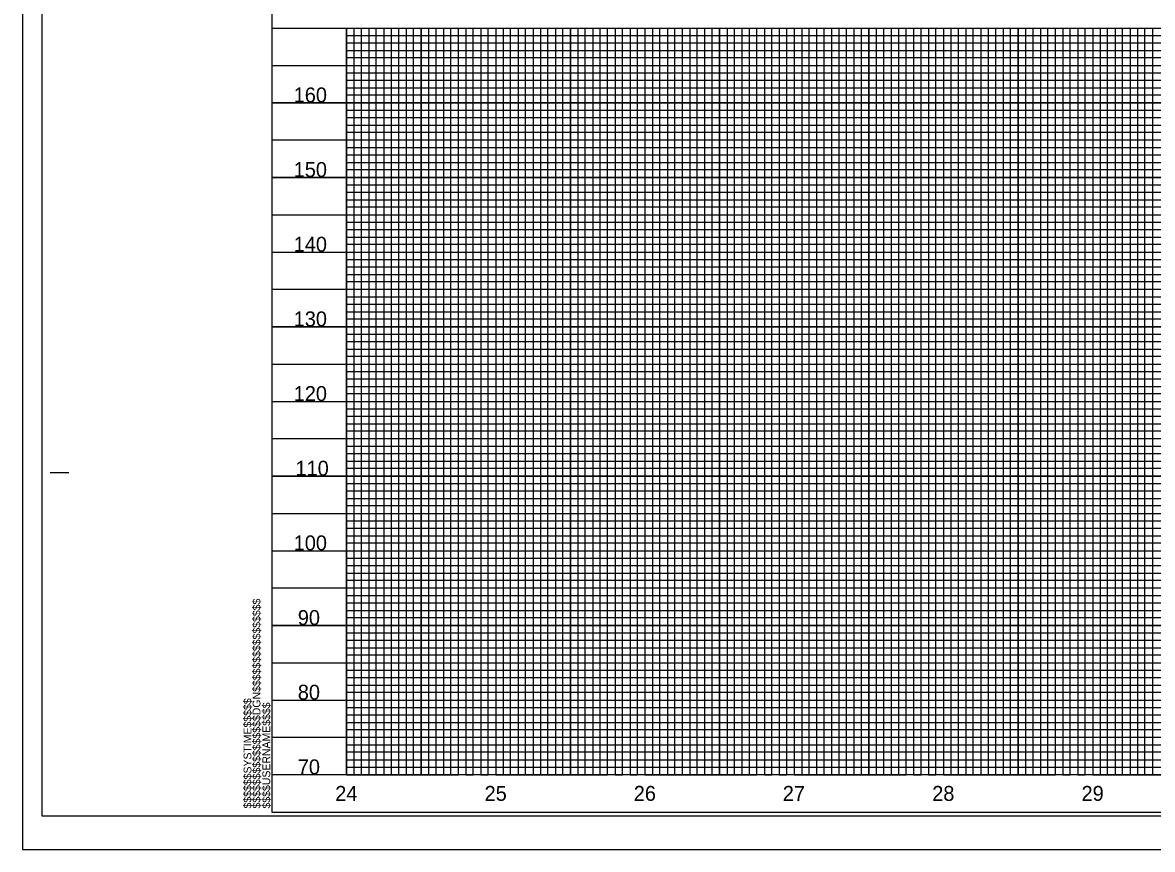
# Model space of a CAD drawing. Extents: x 1779926 to 1781610, y 602514 to 621564.
# Drawn here: x 1779926 to 1780683, y 602514 to 603068 of the extents above; entities that cross this region are included whole.
import ezdxf

# ---------------------------------------------------------------- set-up
doc = ezdxf.new("R2010")
doc.units = 0
for name, color, linetype in [('Exist Vertical Profile Horizontal Axis Label Major', 7, 'Continuous'), ('Exist Vertical Profile Vertical Axis Label', 7, 'Continuous'), ('Scratch_Level_0', 7, 'Continuous'), ('Sheet DOT Grid CELL', 7, 'Continuous'), ('Sheet Layout Profile Border Port 2', 7, 'Continuous'), ('Sheet Plot Border Inside CELL', 7, 'Continuous'), ('Sheet Plot Border Outside CELL', 7, 'Continuous'), ('Sheet Profile CELL', 7, 'Continuous'), ('Sheet Profile Grid Major CELL', 7, 'Continuous'), ('Sheet Profile Grid Middle CELL', 7, 'Continuous'), ('Sheet Profile Grid Minor CELL', 7, 'Continuous')]:
    doc.layers.add(name, color=color, linetype=linetype)

msp = doc.modelspace()

# ---------------------------------------------------------------- linework, layer by layer
at = {"layer": 'Scratch_Level_0'}
msp.add_lwpolyline([(1780142.96, 602564.45), (1780142.96, 603064.45), (1781542.96, 603064.45), (1781542.96, 602564.45)], close=True, dxfattribs=at)
at = {"layer": 'Sheet DOT Grid CELL'}
for p, q in [((1780092.96, 603064.45), (1781592.85, 603064.45)), ((1780142.96, 603064.45), (1780142.96, 602564.45)), ((1780192.96, 603064.45), (1780192.96, 602564.45)), ((1780242.96, 603064.45), (1780242.96, 602564.45)), ((1780292.96, 603064.45), (1780292.96, 602564.45)), ((1780342.96, 603064.45), (1780342.96, 602564.45)), ((1780392.96, 603064.45), (1780392.96, 602564.45)), ((1780442.96, 603064.45), (1780442.96, 602564.45)), ((1780492.96, 603064.45), (1780492.96, 602564.45)), ((1780542.96, 603064.45), (1780542.96, 602564.45)), ((1780592.96, 603064.45), (1780592.96, 602564.45)), ((1780642.96, 603064.45), (1780642.96, 602564.45)), ((1780092.96, 603014.45), (1781592.85, 603014.45)), ((1780092.96, 602964.45), (1781592.85, 602964.45)), ((1780092.96, 602914.45), (1781592.85, 602914.45)), ((1780092.96, 602864.45), (1781592.85, 602864.45)), ((1780092.96, 602814.45), (1781592.85, 602814.45)), ((1780092.96, 602764.45), (1781592.85, 602764.45)), ((1780092.96, 602714.45), (1781592.85, 602714.45)), ((1780092.96, 602664.45), (1781592.85, 602664.45)), ((1780092.96, 602614.45), (1781592.85, 602614.45))]:
    msp.add_line(p, q, dxfattribs=at)
at = {"layer": 'Sheet Layout Profile Border Port 2'}
msp.add_lwpolyline([(1780142.96, 603064.45), (1781542.96, 603064.45), (1781542.96, 602564.45), (1780142.96, 602564.45)], close=True, dxfattribs=at)
msp.add_lwpolyline([(1780142.96, 603064.45), (1781542.96, 603064.45), (1781542.96, 602564.45), (1780142.96, 602564.45)], close=True, dxfattribs=at)
at = {"layer": 'Sheet Plot Border Inside CELL'}
msp.add_lwpolyline([(1779938.96, 602536.9), (1781605.46, 602536.9), (1781605.46, 603592), (1779938.96, 603592)], close=True, dxfattribs=at)
at = {"layer": 'Sheet Plot Border Outside CELL'}
msp.add_lwpolyline([(1779925.96, 602514.45), (1781609.96, 602514.45), (1781609.96, 603614.45), (1779925.96, 603614.45)], close=True, dxfattribs=at)
at = {"layer": 'Sheet Profile CELL'}
for p, q in [((1780092.96, 603064.45), (1781592.96, 603064.45)), ((1779944.46, 602766.95), (1779956.96, 602766.95)), ((1781592.96, 602564.45), (1780092.96, 602564.45)), ((1780092.96, 602539.45), (1781592.96, 602539.45)), ((1780092.96, 602539.45), (1780092.96, 602539.45)), ((1780092.96, 602539.45), (1780092.96, 602539.45)), ((1780092.96, 602539.45), (1780092.96, 602539.45)), ((1780092.96, 602539.45), (1780092.96, 602539.45)), ((1780092.96, 602539.45), (1780092.96, 602539.45)), ((1780092.96, 602539.45), (1780092.96, 602539.45)), ((1780092.96, 602539.45), (1780092.96, 602539.45))]:
    msp.add_line(p, q, dxfattribs=at)
msp.add_lwpolyline([(1781592.96, 603589.45), (1780092.96, 603589.45), (1780092.96, 602539.45), (1781592.96, 602539.45)], close=True, dxfattribs=at)
msp.add_lwpolyline([(1780130.46, 602539.45), (1780130.46, 602539.45)], dxfattribs=at)
at = {"layer": 'Sheet Profile Grid Major CELL'}
for p, q in [((1780592.96, 603064.45), (1780642.96, 603064.45)), ((1780092.96, 602564.45), (1780092.96, 602564.45))]:
    msp.add_line(p, q, dxfattribs=at)
for points in [[(1780142.96, 603064.45), (1780142.96, 602564.45), (1780192.96, 602564.45), (1780192.96, 603064.45), (1780242.96, 603064.45), (1780242.96, 602564.45), (1780292.96, 602564.45), (1780292.96, 603064.45), (1780342.96, 603064.45), (1780342.96, 602564.45), (1780392.96, 602564.45), (1780392.96, 603064.45), (1780442.96, 603064.45), (1780442.96, 602564.45), (1780492.96, 602564.45), (1780492.96, 603064.45), (1780542.96, 603064.45), (1780542.96, 602564.45), (1780592.96, 602564.45), (1780592.96, 603064.45), (1780642.96, 603064.45), (1780642.96, 602564.45), (1780692.96, 602564.45)], [(1781592.96, 603014.45), (1780092.96, 603014.45)], [(1781592.96, 602964.45), (1780092.96, 602964.45), (1780092.96, 602914.45), (1781592.96, 602914.45)], [(1781592.96, 602864.45), (1780092.96, 602864.45), (1780092.96, 602814.45), (1781592.96, 602814.45)], [(1781592.96, 602764.45), (1780092.96, 602764.45), (1780092.96, 602714.45), (1781592.96, 602714.45)], [(1781592.96, 602664.45), (1780092.96, 602664.45), (1780092.96, 602664.45), (1780092.96, 602614.45), (1781592.96, 602614.45)], [(1781592.96, 602564.45), (1780092.96, 602564.45)]]:
    msp.add_lwpolyline(points, dxfattribs=at)
at = {"layer": 'Sheet Profile Grid Middle CELL'}
for points in [[(1780117.96, 603064.45), (1780167.96, 603064.45), (1780167.96, 602564.45), (1780217.96, 602564.45), (1780217.96, 603064.45), (1780267.96, 603064.45), (1780267.96, 602564.45), (1780317.96, 602564.45), (1780317.96, 603064.45), (1780367.96, 603064.45), (1780367.96, 602564.45), (1780417.96, 602564.45), (1780417.96, 603064.45), (1780467.96, 603064.45), (1780467.96, 602564.45), (1780517.96, 602564.45), (1780517.96, 603064.45), (1780567.96, 603064.45), (1780567.96, 602564.45), (1780617.96, 602564.45), (1780617.96, 603064.45), (1780667.96, 603064.45), (1780667.96, 602564.45), (1780717.96, 602564.45)], [(1780092.96, 603039.45), (1781592.96, 603039.45)], [(1781592.96, 602989.45), (1780092.96, 602989.45), (1780092.96, 602939.45), (1781592.96, 602939.45)], [(1781592.96, 602889.45), (1780092.96, 602889.45), (1780092.96, 602839.45), (1781592.96, 602839.45)], [(1781592.96, 602789.45), (1780092.96, 602789.45), (1780092.96, 602739.45), (1781592.96, 602739.45)], [(1781592.96, 602689.45), (1780092.96, 602689.45), (1780092.96, 602639.45), (1781592.96, 602639.45)], [(1781592.96, 602589.45), (1780092.96, 602589.45)]]:
    msp.add_lwpolyline(points, dxfattribs=at)
at = {"layer": 'Sheet Profile Grid Minor CELL'}
for p, q in [((1780142.96, 603059.45), (1781542.96, 603059.45)), ((1781542.96, 603054.45), (1780142.96, 603054.45)), ((1780142.96, 603049.45), (1781542.96, 603049.45)), ((1781542.96, 603044.45), (1780142.96, 603044.45)), ((1780142.96, 603034.45), (1781542.96, 603034.45)), ((1781542.96, 603029.45), (1780142.96, 603029.45)), ((1780142.96, 603024.45), (1781542.96, 603024.45)), ((1781542.96, 603019.45), (1780142.96, 603019.45)), ((1780142.96, 603009.45), (1781542.96, 603009.45)), ((1781542.96, 603004.45), (1780142.96, 603004.45)), ((1780142.96, 602999.45), (1781542.96, 602999.45)), ((1781542.96, 602994.45), (1780142.96, 602994.45)), ((1780142.96, 602984.45), (1781542.96, 602984.45)), ((1781542.96, 602979.45), (1780142.96, 602979.45)), ((1780142.96, 602974.45), (1781542.96, 602974.45)), ((1781542.96, 602969.45), (1780142.96, 602969.45)), ((1780142.96, 602959.45), (1781542.96, 602959.45)), ((1781542.96, 602954.45), (1780142.96, 602954.45)), ((1780142.96, 602949.45), (1781542.96, 602949.45)), ((1781542.96, 602944.45), (1780142.96, 602944.45)), ((1780142.96, 602934.45), (1781542.96, 602934.45)), ((1781542.96, 602929.45), (1780142.96, 602929.45)), ((1780142.96, 602924.45), (1781542.96, 602924.45)), ((1781542.96, 602919.45), (1780142.96, 602919.45)), ((1780142.96, 602909.45), (1781542.96, 602909.45)), ((1781542.96, 602904.45), (1780142.96, 602904.45)), ((1780142.96, 602899.45), (1781542.96, 602899.45)), ((1781542.96, 602894.45), (1780142.96, 602894.45)), ((1780142.96, 602884.45), (1781542.96, 602884.45)), ((1781542.96, 602879.45), (1780142.96, 602879.45)), ((1780142.96, 602874.45), (1781542.96, 602874.45)), ((1781542.96, 602869.45), (1780142.96, 602869.6)), ((1780142.96, 602859.45), (1781542.96, 602859.45)), ((1781542.96, 602854.45), (1780142.96, 602854.45)), ((1780142.96, 602849.45), (1781542.96, 602849.45)), ((1781542.96, 602844.45), (1780142.96, 602844.45)), ((1780142.96, 602834.45), (1781542.96, 602834.45)), ((1781542.96, 602829.45), (1780142.96, 602829.45)), ((1780142.96, 602824.45), (1781542.96, 602824.45)), ((1781542.96, 602819.45), (1780142.96, 602819.45)), ((1780142.96, 602809.45), (1781542.96, 602809.45)), ((1781542.96, 602804.45), (1780142.96, 602804.45)), ((1780142.96, 602799.45), (1781542.96, 602799.45)), ((1781542.96, 602794.45), (1780142.96, 602794.45)), ((1780142.96, 602784.45), (1781542.96, 602784.45)), ((1781542.96, 602779.45), (1780142.96, 602779.45)), ((1780142.96, 602774.45), (1781542.96, 602774.45)), ((1781542.96, 602769.45), (1780142.96, 602769.45)), ((1780142.96, 602759.45), (1781542.96, 602759.45)), ((1781542.96, 602754.45), (1780142.96, 602754.45)), ((1780142.96, 602749.45), (1781542.96, 602749.45)), ((1781542.96, 602744.45), (1780142.96, 602744.45)), ((1780142.96, 602734.45), (1781542.96, 602734.45)), ((1781542.96, 602729.45), (1780142.96, 602729.45)), ((1780142.96, 602724.45), (1781542.96, 602724.45)), ((1781542.96, 602719.45), (1780142.96, 602719.45)), ((1780142.96, 602709.45), (1781542.96, 602709.45)), ((1781542.96, 602704.45), (1780142.96, 602704.45)), ((1780142.96, 602699.45), (1781542.96, 602699.45)), ((1781542.96, 602694.45), (1780142.96, 602694.45)), ((1780142.96, 602684.45), (1781542.96, 602684.45)), ((1781542.96, 602679.45), (1780142.96, 602679.45)), ((1780142.96, 602674.45), (1781542.96, 602674.45)), ((1781542.96, 602669.45), (1780142.96, 602669.45)), ((1780142.96, 602659.45), (1781542.96, 602659.45)), ((1781542.96, 602654.45), (1780142.96, 602654.45)), ((1780142.96, 602649.45), (1781542.96, 602649.45)), ((1781542.96, 602644.45), (1780142.96, 602644.45)), ((1780142.96, 602634.45), (1781542.96, 602634.45)), ((1781542.96, 602629.45), (1780142.96, 602629.45)), ((1780142.96, 602624.45), (1781542.96, 602624.45)), ((1781542.96, 602619.45), (1780142.96, 602619.45)), ((1780142.96, 602609.45), (1781542.96, 602609.45)), ((1781542.96, 602604.45), (1780142.96, 602604.45)), ((1780142.96, 602599.45), (1781542.96, 602599.45)), ((1781542.96, 602594.45), (1780142.96, 602594.45)), ((1780142.96, 602584.45), (1781542.96, 602584.45)), ((1781542.96, 602579.45), (1780142.96, 602579.45)), ((1780142.96, 602574.45), (1781542.96, 602574.45)), ((1780142.96, 602569.45), (1781542.96, 602569.45))]:
    msp.add_line(p, q, dxfattribs=at)
for points in [[(1780142.96, 603064.45), (1780147.96, 603064.45), (1780147.96, 602564.45), (1780152.96, 602564.45), (1780152.96, 603064.45), (1780157.96, 603064.45), (1780157.96, 602564.45), (1780162.96, 602564.45), (1780162.96, 603064.45), (1780172.96, 603064.45), (1780172.96, 602564.45), (1780177.96, 602564.45), (1780177.96, 603064.45), (1780182.96, 603064.45), (1780182.96, 602564.45), (1780187.96, 602564.45), (1780197.96, 602564.45), (1780202.96, 602564.45), (1780202.96, 603064.45), (1780207.96, 603064.45), (1780207.96, 602564.45), (1780212.96, 602564.45), (1780212.96, 603064.45), (1780222.96, 603064.45), (1780222.96, 602564.45), (1780227.96, 602564.45), (1780227.96, 603064.45), (1780232.96, 603064.45), (1780232.96, 602564.45), (1780237.96, 602564.45), (1780237.96, 603064.45), (1780247.96, 603064.45), (1780247.96, 602564.45), (1780252.96, 602564.45), (1780252.96, 603064.45), (1780257.96, 603064.45), (1780257.96, 602564.45), (1780262.96, 602564.45), (1780262.96, 603064.45), (1780272.96, 603064.45), (1780272.96, 602564.45), (1780277.96, 602564.45), (1780277.96, 603064.45), (1780282.96, 603064.45), (1780282.96, 602564.45), (1780287.96, 602564.45), (1780287.96, 603064.45), (1780297.96, 603064.45), (1780297.96, 602564.45), (1780302.96, 602564.45), (1780302.96, 603064.45), (1780307.96, 603064.45), (1780307.96, 602564.45), (1780312.96, 602564.45), (1780312.96, 603064.45), (1780322.96, 603064.45), (1780322.96, 602564.45), (1780327.96, 602564.45), (1780327.96, 603064.45), (1780332.96, 603064.45), (1780332.96, 602564.45), (1780337.96, 602564.45), (1780337.96, 603064.45), (1780347.96, 603064.45), (1780347.96, 602564.45), (1780352.96, 602564.45), (1780352.96, 603064.45), (1780357.96, 603064.45), (1780357.96, 602564.45)], [(1780187.96, 602564.45), (1780187.96, 603064.45), (1780197.96, 603064.45), (1780197.96, 602564.45)], [(1780357.96, 602564.45), (1780362.96, 602564.45), (1780362.96, 603064.45), (1780372.96, 603064.45), (1780372.96, 602564.45), (1780377.96, 602564.45), (1780377.96, 603064.45), (1780382.96, 603064.45), (1780382.96, 602564.45), (1780387.96, 602564.45), (1780387.96, 603064.45), (1780397.96, 603064.45), (1780397.96, 602564.45), (1780402.96, 602564.45), (1780402.96, 603064.45), (1780407.96, 603064.45), (1780407.96, 602564.45), (1780412.96, 602564.45), (1780412.96, 603064.45), (1780422.96, 603064.45), (1780422.96, 602564.45), (1780427.96, 602564.45), (1780427.96, 603064.45), (1780432.96, 603064.45), (1780432.96, 602564.45), (1780437.96, 602564.45), (1780437.96, 603064.45), (1780447.96, 603064.45), (1780447.96, 602564.45), (1780452.96, 602564.45), (1780452.96, 603064.45), (1780457.96, 603064.45), (1780457.96, 602564.45), (1780462.96, 602564.45), (1780462.96, 603064.45), (1780472.96, 603064.45), (1780472.96, 602564.45), (1780477.96, 602564.45), (1780477.96, 603064.45), (1780482.96, 603064.45), (1780482.96, 602564.45), (1780487.96, 602564.45), (1780487.96, 603064.45), (1780497.96, 603064.45), (1780497.96, 602564.45), (1780502.96, 602564.45), (1780502.96, 603064.45), (1780507.96, 603064.45), (1780507.96, 602564.45), (1780512.96, 602564.45), (1780512.96, 603064.45), (1780522.96, 603064.45), (1780522.96, 602564.45), (1780527.96, 602564.45), (1780527.96, 603064.45), (1780532.96, 603064.45), (1780532.96, 602564.45), (1780537.96, 602564.45), (1780537.96, 603064.45), (1780547.96, 603064.45), (1780547.96, 602564.45), (1780552.96, 602564.45), (1780552.96, 603064.45), (1780557.96, 603064.45), (1780557.96, 602564.45), (1780562.96, 602564.45), (1780562.96, 603064.45), (1780572.96, 603064.45), (1780572.96, 602564.45), (1780577.96, 602564.45), (1780577.96, 603064.45), (1780582.96, 603064.45), (1780582.96, 602564.45), (1780587.96, 602564.45), (1780587.96, 603064.45), (1780597.96, 603064.45), (1780597.96, 602564.45), (1780602.96, 602564.45), (1780602.96, 603064.45), (1780607.96, 603064.45), (1780607.96, 602564.45), (1780612.96, 602564.45), (1780612.96, 603064.45), (1780622.96, 603064.45), (1780622.96, 602564.45), (1780627.96, 602564.45), (1780627.96, 603064.45), (1780632.96, 603064.45), (1780632.96, 602564.45), (1780637.96, 602564.45), (1780637.96, 603064.45), (1780647.96, 603064.45), (1780647.96, 602564.45), (1780652.96, 602564.45), (1780652.96, 603064.45), (1780657.96, 603064.45), (1780657.96, 602564.45), (1780662.96, 602564.45), (1780662.96, 603064.45), (1780672.96, 603064.45)], [(1780672.96, 603064.45), (1780672.96, 602564.45), (1780677.96, 602564.45), (1780677.96, 603064.45), (1780682.96, 603064.45), (1780682.96, 602564.45), (1780687.96, 602564.45)]]:
    msp.add_lwpolyline(points, dxfattribs=at)

# ---------------------------------------------------------------- texts
at = {"layer": 'Exist Vertical Profile Horizontal Axis Label Major'}
for s, p in [('24', (1780135.41, 602546.95)), ('25', (1780235.5, 602546.95)), ('26', (1780335.44, 602546.95)), ('27', (1780435.3, 602546.95)), ('28', (1780535.43, 602546.95)), ('29', (1780635.47, 602546.95))]:
    msp.add_text(s, height=10, dxfattribs=at).set_placement(p)
at = {"layer": 'Exist Vertical Profile Vertical Axis Label'}
for s, p in [('160', (1780107.59, 603014.7)), ('150', (1780107.59, 602964.7)), ('140', (1780107.59, 602914.7)), ('130', (1780107.59, 602864.7)), ('120', (1780107.59, 602814.7)), ('110', (1780108.79, 602764.7)), ('100', (1780107.59, 602714.7)), ('90', (1780110.35, 602664.7)), ('80', (1780110.35, 602614.7)), ('70', (1780110.35, 602564.7))]:
    msp.add_text(s, height=10, dxfattribs=at).set_placement(p)
at = {"layer": 'Sheet Profile CELL'}
for s, p in [('$$$$$$$$$$$$$$$$DGN$$$$$$$$$$$$$$$$', (1780085.32, 602541.83)), ('$$$$$$SYSTIME$$$$$', (1780079.27, 602541.83)), ('$$$$USERNAME$$$$', (1780091.9, 602541.84))]:
    msp.add_text(s, height=5.25, rotation=90, dxfattribs=at).set_placement(p)

doc.saveas('drawing.dxf')
